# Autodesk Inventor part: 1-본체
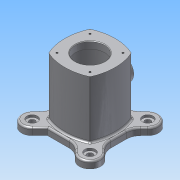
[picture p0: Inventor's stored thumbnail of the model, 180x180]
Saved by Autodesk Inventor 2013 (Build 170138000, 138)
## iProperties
Created: 2016-05
Part Number: 1-본체
Material: 알루미늄 6061
Document SubType Name: Modeling
Designer: Administrator
Density: 2.71 g/cm^3
Mass: 1114.01 g
Surface Area: 865.484 cm^2
Volume: 411.075 cm^3
Author: Administrator
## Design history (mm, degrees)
sketch "스케치1"
  geometry: L1 (-43, 0)-(43, 0); L2 (0, 43)-(0, -43); A1 r 50 centre (0, 0) between (35.355, 35.355) and (-35.355, 35.355); A2 r 85.579 centre (0, -42.579) between (35.355, 35.355) and (-35.355, 35.355); A3 r 85.579 centre (42.579, 0) between (-35.355, 35.355) and (-35.355, -35.355); A4 r 85.579 centre (0, 42.579) between (-35.355, -35.355) and (35.355, -35.355); A5 r 85.579 centre (-42.579, 0) between (35.355, -35.355) and (35.355, 35.355); 1 further point
  constraints: 16 point on circle, 5 centre point, 4 end point, 3 equal radius, 2 horizontal alignment, 2 vertical alignment, 1 coincident
  dimensions: "d5" = 100 diameter of A1; "d7" = 86 distance of L1.start L1.end; "d8" = 86 distance of L2.start L2.end
extrude "돌출1" new body sketch "스케치1" distance "d9" = 98; taper "d10" = 0 deg
sketch "스케치2"
  geometry: C1 r 25 at (0, 0); 1 further point
  constraints: 1 centre point, 1 coincident
  dimensions: "d11" = 50 diameter of C1
extrude "돌출2" cut sketch "스케치2" distance "d13" = 98; taper "d14" = 0 deg
sketch "스케치3" dims "d15" = 140
  geometry: L1 (0, 0)-(-49.497, 49.497); L2 (0, 0)-(0, 70); L3 (-49, 23.544)-(-49, -23.544); L4 (49, 23.544)-(49, -23.544); L5 (-23.544, -49)-(23.544, -49); L6 (-23.544, 49)-(23.544, 49); L7 (-62.225, 36.77)-(-49, 23.544); L8 (-36.77, 62.225)-(-23.544, 49); L9 (0, 25.456)-(0.46, 24.996); L10 (-49.497, -49.497)-(0, 0); L11 (0, 0)-(49.497, -49.497); L12 (0, 0)-(49.497, 49.497); L13 (49, 23.544)-(62.225, 36.77); L14 (-0.46, 24.996)-(0, 25.456); L15 (23.544, 49)-(36.77, 62.225); L16 (-49, -23.544)-(-62.225, -36.77); L17 (-23.544, -49)-(-36.77, -62.225); L18 (23.544, -49)-(36.77, -62.225); L19 (49, -23.544)-(62.225, -36.77); C1 r 5 at (-49.497, -49.497); C2 r 5 at (-49.497, 49.497); C3 r 5 at (49.497, 49.497); C4 r 5 at (49.497, -49.497); A1 r 25 centre (0, 0) between (0.46, 24.996) and (-0.46, 24.996) reference; A2 r 18 centre (-49.497, 49.497) between (-35.239, 60.483) and (-60.483, 35.239); A3 r 18 centre (49.497, 49.497) between (60.483, 35.239) and (35.239, 60.483); A4 r 18 centre (49.497, -49.497) between (35.239, -60.483) and (60.483, -35.239); A5 r 18 centre (-49.497, -49.497) between (-60.483, -35.239) and (-35.239, -60.483)
  constraints: 38 end point, 18 point on circle, 12 parallel, 10 tangent, 8 centre point, 5 coincident, 5 equal radius, 2 horizontal alignment, 2 perpendicular, 2 vertical alignment, 1 horizontal, 1 point on line, 1 vertical, 15 other
  dimensions: "d17" = 36 diameter of A2; "d18" = 45 deg angle of L2 L1; "d19" = 98 distance between parallel lines of L3 L4; "d20" = 49 distance from line of L1.start L3; "d21" = 98 distance between parallel lines of L6 L5; "d22" = 49 distance from line of A1.centre L6; "d23" = 10 diameter of C1; "d24" = 10 diameter of C2
extrude "돌출3" join sketch "스케치3" distance "d25" = 12; taper "d26" = 0 deg
fillet "모깎기1" dims "d27" = 25
node "작업 평면1"
sketch "스케치4"
  geometry: C1 r 35 at (0, 0); 1 further point
  constraints: 1 centre point, 1 coincident
  dimensions: "d29" = 70 diameter of C1
extrude "돌출4" cut sketch "스케치4" distance "d31" = 86; taper "d32" = 0 deg
node "작업 평면2"
sketch "스케치5"
  geometry: C1 r 12.5 at (0, 49); 1 further point
  constraints: 1 centre point, 1 vertical alignment
  dimensions: "d34" = 25 diameter of C1; "d36" = 49 distance of point (0, 0) C1.centre
extrude "돌출5" cut sketch "스케치5" stored distance "d37" = 86; taper "d38" = 0 deg
sketch "스케치7"
  geometry: L1 (43, 36.5)-(35, 36.5) reference; L2 (43, 0)-(43, 98) reference; L3 (43, 49)-(55, 49); L4 (55, 34)-(55, 29); L5 (55, 29)-(35, 25.473); L6 (55, 34)-(47, 34); L7 (47, 34)-(47, 36.5); L8 (47, 36.5)-(43, 36.5); L9 (35, 86)-(35, 0) reference; 1 further point
  constraints: 12 end point, 4 perpendicular, 1 horizontal, 1 midpoint, 1 point on line
  dimensions: "d39" = 55 distance from line of point (0, 0) L4; "d40" = 100 deg angle of L2 L5; "d41" = 20 distance from line of L3 L4.end; "d42" = 8 distance of L4.start L6.end; "d43" = 15 distance between parallel lines of L3 L6
revolve "회전1" sketch "스케치7" stored, may be unused: angle "d44" = 90 deg
sketch "스케치8"
  geometry: L1 (0, 0)-(0, 40); L2 (0, 0)-(-28.283, 28.285); C1 r 25 at (0, 0) reference; A1 r 40 centre (0, 0) between (-28.283, 28.285) and (0, 40)
  constraints: 4 end point, 2 point on circle, 1 centre point, 1 coincident, 1 vertical
  dimensions: "d45" = 80 diameter of A1; "d49" = 44.9983 deg angle of L1 L2
hole "구멍1" sketch "스케치8" at (-28.283, 28.285) diameter "d51" = 3.242; stored, may be unused: countersink angle "d55" = 90 deg, drill point angle "d57" = 118 deg; dims "d52" = 7, "d53" = 4, "d54" = 2, "d56" = 10
sketch "스케치9"
  geometry: L1 (13.189, 49)-(-13.189, 49) reference; L2 (0, 0)-(28.284, 28.284); L3 (0, 0)-(0, 40); A1 r 25 centre (0, 0) between (-0.46, 24.996) and (-0.46, 24.996) reference; A2 r 40 centre (0, 0) between (28.284, 28.284) and (0, 40)
  constraints: 4 end point, 2 point on circle, 1 centre point, 1 coincident, 1 perpendicular
  dimensions: "d61" = 80 diameter of A2; "d63" = 45 deg angle of L2 L3
hole "구멍2" sketch "스케치9" at (28.284, 28.284) diameter "d65" = 3.242; stored, may be unused: countersink angle "d69" = 90 deg, drill point angle "d71" = 118 deg; dims "d66" = 7, "d67" = 4, "d68" = 2, "d70" = 10
node "작업 평면3"
sketch "스케치10"
  geometry: L1 (35.355, 98)-(-35.355, 98) reference; 2 further points
  constraints: 1 other
  dimensions: "d76" = 49 distance from line of L1 point (-29, 49); "d77" = 29 horizontal distance of point (0, 0) point (-29, 49)
feature "엠보싱1" sketch "스케치10" dims "d78" = 0.5, "d79" = 0
sketch "스케치11"
  geometry: C1 r 5 at (-49.497, -49.497) reference; C2 r 5 at (-49.497, 49.497) reference; C3 r 5 at (49.497, 49.497) reference; C4 r 5 at (49.497, -49.497) reference; C5 r 9 at (-49.497, 49.497); C6 r 9 at (49.497, 49.497); C7 r 9 at (49.497, -49.497); C8 r 9 at (-49.497, -49.497); A1 r 18 centre (49.497, 49.497) between (62.225, 36.77) and (36.77, 62.225) reference; A2 r 18 centre (-49.497, 49.497) between (-36.77, 62.225) and (-62.225, 36.77) reference; A3 r 18 centre (-49.497, -49.497) between (-62.225, -36.77) and (-36.77, -62.225) reference; A4 r 18 centre (49.497, -49.497) between (36.77, -62.225) and (62.225, -36.77) reference; 1 further point
  constraints: 4 centre point, 4 coincident, 3 equal radius
  dimensions: "d80" = 18 diameter of C8
extrude "돌출6" cut sketch "스케치11" distance "d82" = 4; taper "d83" = 0 deg
chamfer "모따기1" distance "d84" = 1; stored, may be unused: second distance "d85" = 2, angle "d86" = 45 deg
fillet "모깎기2" dims "d87" = 3
chamfer "모따기2" distance "d88" = 1; stored, may be unused: second distance "d89" = 2, angle "d90" = 45 deg
node "솔리드1"
pattern_circular "원형 패턴1" dims angle "d59" = 360 deg
pattern_circular "원형 패턴2" dims angle "d73" = 360 deg
other parameters: "d28" = -12, "d33" = 55, "d75" = 72.25
